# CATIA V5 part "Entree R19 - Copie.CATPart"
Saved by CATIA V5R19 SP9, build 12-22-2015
Part number: entree
Bounding box of the stored display mesh (mm): x -13.996 to 13.996, y -15 to 21.5, z -13.996 to 13.996
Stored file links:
  C:\Users\hbezard\Documents\Perso\imprimante 3d\pieces\rincepot\Entree R19 - Copie.CATPart
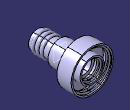
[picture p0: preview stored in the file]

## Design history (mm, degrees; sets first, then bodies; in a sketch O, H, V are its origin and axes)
Parameters
  `dia admi` = 22
  `dia evac` = 10
  `paroies hp` = 2
  `paroies bp` = 2
  `longueur filetee` = 5
  `pas jonction` = 2
  `prof filet jonction` = 1
  `dia gourde` = 12
  `pas gourde` = 2
  `entree gourde` = 8
  `longueur jonction` = 30
  `dia injection` = 8
  `longueur injection` = 110
  `longueur gourde` = 30
  `dia inter injection` = 6
  Real = 0
Body1 (main body)
  Sketch1 on yz-plane, origin (0, 0, 0), H (0, 1, 0), V (0, 0, 1)
    line L1 (-15, 6) -> (-13, 6)
    line L2 (0, 6) -> (0, 8)
    line L3 (16, 8) -> (21.5, 8)
    line L4 (21.5, 8) -> (21.5, 7)
    line L5 (21.5, 7) -> (16, 7)
    line L6 (16, 7) -> (16, 5)
    line L7 (16, 5) -> (0, 5)
    axis line L8 (-32.3822, 0) -> (183.7177, 0)
    line L9 (12, 14) -> (21.5, 14)
    line L10 (21.5, 14) -> (21.5, 13)
    line L11 (21.5, 13) -> (16, 13)
    line L12 (16, 13) -> (16, 8)
    point P13 (-31.9622, 57.8884)
    reference intersected line E1 through (0, 0) direction (-1, 0) from xy-plane
    line L13 (12, 8) -> (0, 8)
    line L14 (0, 5) -> (-15, 5)
    line L15 (-15, 5) -> (-15, 6)
    point P18 (-15, 6)
    line L16 (12, 8) -> (12, 14)
    reference intersected line E2 through (0, 0) direction (0, 1) from zx-plane
    reference intersected line E3 through (0, 0) direction (0, 1) from zx-plane
    arc A1 centre (-12, 6) radius 1 from (-11, 6) to (-13, 6) ccw
    point P20 (-12, 6)
    point P21 (-10, 6)
    point P22 (-8, 6)
    point P23 (-9, 6)
    arc A2 centre (-9, 6) radius 1 from (-8, 6) to (-10, 6) ccw
    point P24 (-7, 6)
    point P25 (-5, 6)
    point P26 (-6, 6)
    arc A3 centre (-6, 6) radius 1 from (-5, 6) to (-7, 6) ccw
    reference intersected line E4 through (0, 0) direction (0, 1) from zx-plane
    line L17 (-5, 6) -> (0, 6)
    line L18 (-8, 6) -> (-7, 6)
    line L19 (-11, 6) -> (-10, 6)
    distance L1 L7 = 1
    distance L7 L8 = 5
    length L5 = 5.5
    distance L3 L5 = 1 {= Sketch1.distance(L1 L7)}
    length L11 = 5.5
    distance L9 L11 = 1 {= `détruit_LENGTH`}
    distance L5 L1 = 1
    distance L9 L3 = 6
    distance L6 E2 = 16
    length L2 = 2
    distance L16 L12 = 4
    radius A1 = 1
    distance L15 P20 = 3
    distance L15 P23 = 6
    distance L15 P26 = 9
    radius A2 = 1
    radius A3 = 1
    distance P25 L1 = 0
    distance P24 L1 = 0
    distance P22 L1 = 0
    distance P21 L1 = 0
    distance L15 E4 = 15
    horizontal: L1 H, L3 H, L5 H, L7 H, L8 H, L9 H, L11 H, L14 H, L13 H
    vertical: L4 V, L10 V, L15 V, L16 V, L2 V, L12 V
    parallelism: L6 L2
    coincidence: L8 E1, L10 L4, P18 L1, P18 L15, L2 E3, P20 L1, P23 L1, P26 L1, L1 L17, L1 L18, L1 L19, P25 A3, P24 A3, P22 A2, P21 A2
  Shaft1 "jonction": profile Sketch1, axis Sketch1.L8, angle 360
  Plane1: type Offset, RefPlane xy-plane, Offset 20
  Sketch2 on Plane1, origin (0, 0, 20), H (1, 0, 0), V (0, 1, 0)
    point P1 (0, 15)
    reference intersected line E1 through (0, 0) direction (0, 1) from yz-plane
    reference intersected line E2 through (0, 0) direction (-1, 0) from zx-plane
    circle A1 centre (0, 15) radius 3
    distance P1 E2 = 15
    radius A1 = 3
    coincidence: P1 E1
  Pocket1: profile unresolved, up to face of Shaft1, deactivated
  Pad1: profile Sketch2, direction (0, 0, -1), up to face of Shaft1 from Sketch1.L3, opposite side length 100, deactivated
  Sketch3 on Plane1, origin (0, 0, 20), H (1, 0, 0), V (0, 1, 0)
    circle A1 centre (0, 15) radius 2
    reference projected point E1 (0, 15) from axis of face of Pad1 from Sketch2.A1
    reference projected circle E2 centre (0, 15) radius 3 from Sketch2.A1
    distance A1 E2 = 1
    concentricity: A1 E1
  Pocket2: profile Sketch3, direction (0, 0, -1), through (limit type 6), opposite side length 98, deactivated
  Plane2: type Angle, RefPlane yz-plane, Direction Y axis, Angle -30
  Plane3: type Offset, RefPlane {inverselocal InverseElem Plane2}, Offset 10, reversed
  Sketch4 on Plane3, origin (-4.0798, 0, 27.0665), H (0, -1, 0), V (-0.5, 0, 0.866)
    line L1 (-18.1996, -23.9802) -> (-19.5373, -23.9802)
    line L2 (-19.5373, -23.9802) -> (-19.5373, -26.9802)
    line L3 (-19.5373, -26.9802) -> (-18.1996, -26.9802)
    line L4 (-18.1996, -26.9802) -> (-18.1996, -23.9802)
    point P5 (-24, -23.9802)
    line L5 (-24, -23.9802) -> (-22.6623, -23.9802)
    line L6 (-22.6623, -23.9802) -> (-22.6623, -26.9802)
    line L7 (-22.6623, -26.9802) -> (-24, -26.9802)
    line L8 (-24, -26.9802) -> (-24, -23.9802)
    point P7 (-22.6623, -26.9802)
    reference intersected line E1 through (-12.1996, 0) direction (0, -1) from face of Shaft1
    reference intersected line E2 through (-30, 0) direction (0, -1) from face of Shaft1 from Sketch1.L10
    reference projected line E3 through (0, -25.4802) direction (-1, 0) from axis of face of Shaft1 from Sketch1.L7
    length L3 = 1.3377
    length L7 = 1.3377 {= Sketch4.length(L3)}
    distance L3 L1 = 3
    distance L4 E1 = 6
    distance L8 E2 = 6
    horizontal: L1 H, L3 H, L5 H, L7 H
    vertical: L2 V, L4 V, L6 V, L8 V
    coincidence: P5 L1, P7 L3
    symmetry: L3 L1 E3
  Pad2: profile Sketch4, direction (-0.866, 0, -0.5), up to face of Shaft1 from Sketch1.L3, opposite side up to face of Shaft1, deactivated
  Mirror1: of Pad2, about yz-plane, deactivated
  Plane4: type Offset, RefPlane xy-plane, Offset 10, reversed
  Sketch5 on Plane4, origin (0, 0, -10), H (1, 0, 0), V (0, 1, 0)
    point P1 (0, 20.1996)
    line L1 (1, 22.1996) -> (1, 18.1996)
    line L2 (1, 18.1996) -> (-1, 18.1996)
    line L3 (-1, 18.1996) -> (-1, 22.1996)
    line L4 (-1, 22.1996) -> (1, 22.1996)
    point P6 (0, 22)
    line L5 (1, 24) -> (1, 20)
    line L6 (1, 20) -> (-1, 20)
    line L7 (-1, 20) -> (-1, 24)
    line L8 (-1, 24) -> (1, 24)
    point P8 (1, 20)
    reference projected line E1 through (0, 0) direction (0, 1) from axis of face of Shaft1 from Sketch1.L7
    reference intersected line E2 through (0, 12.1996) direction (-1, 0) from face of Shaft1
    reference projected line E3 (-13, 30) -> (13, 30) from edge [face of Shaft1 from Sketch1.L9 | face of Shaft1 from Sketch1.L10]
    length L3 = 4
    length L7 = 4 {= Sketch5.length(L3)}
    length L4 = 2
    distance L2 E2 = 6
    distance L8 E3 = 6
    vertical: L1 V, L3 V, L5 V, L7 V
    horizontal: L2 H, L4 H, L6 H, L8 H
    equidistance: L1 L3 P1, L2 L4 P1, L5 L7 P6, L6 L8 P6
    coincidence: P8 L1, P1 E1, L7 L3
  Pad3: profile Sketch5, direction (0, 0, 1), up to face of Shaft1 from Sketch1.L3, opposite side up to face of Shaft1, deactivated
  Fillet1: radius 0.5, on face of Pad3 from Sketch5.L2; face of Pad3 from Sketch5.L1; face of Pad3 from Sketch5.L3; face of Pad3 from Sketch5.L4; face of Pad3 from Sketch5.L8; face of Pad3 from Sketch5.L5; face of Pad3 from Sketch5.L6; face of Pad3 from Sketch5.L7, deactivated
  Fillet2: radius 0.5, on face of Pad2 from Sketch4.L8; face of Pad2 from Sketch4.L7; face of Pad2 from Sketch4.L5; face of Pad2 from Sketch4.L6; face of Pad2 from Sketch4.L4; face of Pad2 from Sketch4.L3; face of Pad2 from Sketch4.L1; face of Pad2 from Sketch4.L2; face of Mirror1 (x8), deactivated
  Fillet3: radius 0.5, on edge [face of Shaft1 from Sketch1.L3 | face of Pad1 from Sketch2.A1], deactivated
  Helix1: Direction Y axis, RefPoint {point type Coord, X 0, Y -1.155, Z 0, RefPoint vertex [element of Sketch1 | element of Sketch1]}, Pitch 2, Height 3.5, TaperAngle 0
  Sketch6 on yz-plane, origin (0, 0, 0), H (0, 1, 0), V (0, 0, 1)
    point P1 (3.7679, 12)
    line L1 (3.7679, 12) -> (4.9226, 12)
    point P2 (4.9226, 12)
    line L2 (4.9226, 12) -> (4.3453, 13)
    point P3 (4.3453, 13)
    line L3 (4.3453, 13) -> (3.7679, 12)
    axis line L4 (4.3453, 15.5745) -> (4.3453, 9.1301)
    reference projected line E1 (5.5, 12) -> (0, 12) from edge of Sketch1
    reference projected line E2 (5.5, 14) -> (5.5, -14) from edge [face of Shaft1 | face of Shaft1 from Sketch1.L9]
    length L4 = 6.4444
    angle L2 L1 = 60
    distance L1 P3 = 1
    distance L1 E1 = 0
    distance L4 E2 = 1.1547 {= Sketch6.length(L1)}
    length L1 = 1.1547 (reference)
    horizontal: L1 H
    vertical: L4 V
    symmetry: P2 P1 L4
    coincidence: P3 L4
  Rib1: profile Sketch6, centre curve Helix1, deactivated
  Fillet4: radius 0.5, on face of Rib1, deactivated
  Fillet5: radius 0.5, on face of Rib1, deactivated
  Helix2: Direction Y axis, RefPoint vertex [element of Sketch1 | element of Sketch1], Pitch 2, Height 4, TaperAngle 0
  Sketch7 on yz-plane, origin (0, 0, 0), H (0, 1, 0), V (0, 0, 1)
    point P1 (0, 6)
    line L1 (0, 6) -> (1.1547, 6)
    point P2 (1.1547, 6)
    line L2 (1.1547, 6) -> (0.5774, 7)
    point P3 (0.5774, 7)
    line L3 (0.5774, 7) -> (0, 6)
    axis line L4 (0.5774, 18.6338) -> (0.5774, 12.1894)
    reference projected point E1 (0, 6) from vertex [element of Sketch1 | element of Sketch1]
    length L4 = 6.4444
    angle L2 L1 = 60
    distance L1 P3 = 1
    horizontal: L1 H
    vertical: L4 V
    symmetry: P2 P1 L4
    coincidence: P3 L4, P1 E1
  Rib2: profile Sketch7, centre curve Helix2, deactivated
  Fillet6: radius 0.5, on face of Rib2, deactivated
  Fillet7: radius 0.5, on face of Rib2, deactivated
  Sketch8 on yz-plane, origin (0, 0, 0), H (0, 1, 0), V (0, 0, 1)
    point P1 (21.5, 13)
    line L1 (21.5, 13) -> (20.3453, 13)
    point P2 (20.3453, 13)
    line L2 (20.3453, 13) -> (20.9226, 12)
    point P3 (20.9226, 12)
    line L3 (20.9226, 12) -> (21.5, 13)
    axis line L4 (20.9226, 19.8788) -> (20.9226, 13.4344)
    reference projected point E1 (21.5, 13) from vertex [element of Sketch1 | element of Sketch1]
    length L4 = 6.4444
    angle L2 L1 = 60
    distance L1 P3 = 1
    horizontal: L1 H
    vertical: L4 V
    symmetry: P2 P1 L4
    coincidence: P3 L4, P1 E1
  Sketch9 on yz-plane, origin (0, 0, 0), H (0, 1, 0), V (0, 0, 1)
    point P1 (21.5, 7)
    line L1 (21.5, 7) -> (20.3453, 7)
    point P2 (20.3453, 7)
    line L2 (20.3453, 7) -> (20.9226, 6)
    point P3 (20.9226, 6)
    line L3 (20.9226, 6) -> (21.5, 7)
    axis line L4 (20.9226, 13.8788) -> (20.9226, 7.4344)
    reference projected point E1 (21.5, 7) from vertex [element of Sketch1 | element of Sketch1]
    length L4 = 6.4444
    angle L2 L1 = 60
    distance L1 P3 = 1
    horizontal: L1 H
    vertical: L4 V
    symmetry: P2 P1 L4
    coincidence: P3 L4, P1 E1
  Helix3: Direction Y axis, RefPoint vertex [element of Sketch1 | element of Sketch1], Pitch 2, Height 4, TaperAngle 0
  Helix4: Direction Y axis, RefPoint vertex [element of Sketch1 | element of Sketch1], Pitch 2, Height 4, TaperAngle 0
  Rib3: profile Sketch8, centre curve Helix3
  Rib4: profile Sketch9, centre curve Helix4
  Fillet8: radius 0.5, on face of Rib3
  Fillet9: radius 0.5, on face of Rib4
  Fillet10: radius 0.5, on face of Rib4
  Fillet11: radius 0.5, on face of Rib3
  Sketch10 on start face of Pad1, origin (0, 0, 120), H (1, 0, 0), V (0, 1, 0)
    point P1 (0, 0)
  Hole1: placed by Sketch10, at (0, 15, 120) direction (0, 0, -1), diameter 1, through (limit type 6), deactivated
  Point1: type OnCurve, Support edge [face of Pad1 from Sketch2.A1 | start face of Pad1], RefPoint {extremum Reference edge [face of Pad1 from Sketch2.A1 | start face of Pad1], Direction (1, 2, 3)}, Ratio 0.5
  Sketch11 on yz-plane, origin (0, -0.7113, -0.4445), H (0, 1, 0), V (0, 0, 1)
    point P1 (15.7113, 116.4445)
    reference projected line E1 through (15.7113, 0) direction (0, 1) from axis of face of Pad1 from Sketch2.A1
    reference intersected line E2 (12.7113, 120.4445) -> (18.7113, 120.4445) from start face of Pad1
    distance P1 E2 = 4
    coincidence: P1 E1
  Hole2: placed by Sketch11, at (0, 15, 116) direction (-1, 0, 0), diameter 1, through (limit type 3), deactivated
  CircPattern1: of Hole2, instances 8, angular step 45, deactivated
  RectPattern1: of CircPattern1, direction 1 instances 10, spacing 9, along Z axis reversed, deactivated
Body2
  Solid1: linked copy from another document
